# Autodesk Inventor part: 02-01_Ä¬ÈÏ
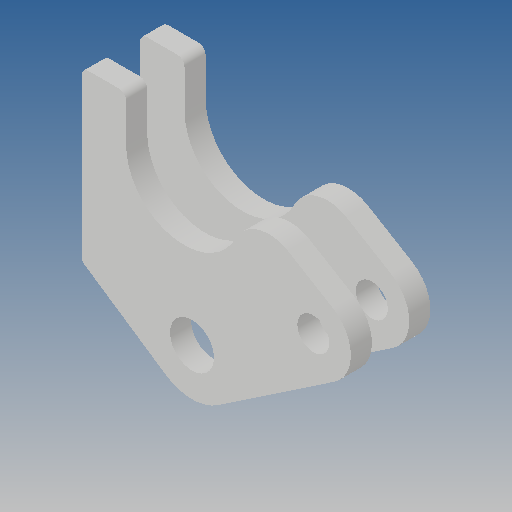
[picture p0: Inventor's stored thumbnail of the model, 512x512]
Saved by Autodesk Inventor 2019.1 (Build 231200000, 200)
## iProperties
Created: 2010-06
Part Number: 02-01_Ä¬ÈÏ
Material: Ogólny
Document SubType Name: Modeling
Designer: CADENGINEERING4
Density: 1 g/cm^3
Appearance: Domyślna
Author: CADENGINEERING4
Revision Number: ÈÎºÎ
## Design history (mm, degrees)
feature "NONE"
feature "NONE:1"
node "Bryła1"
node "Bryła2"
